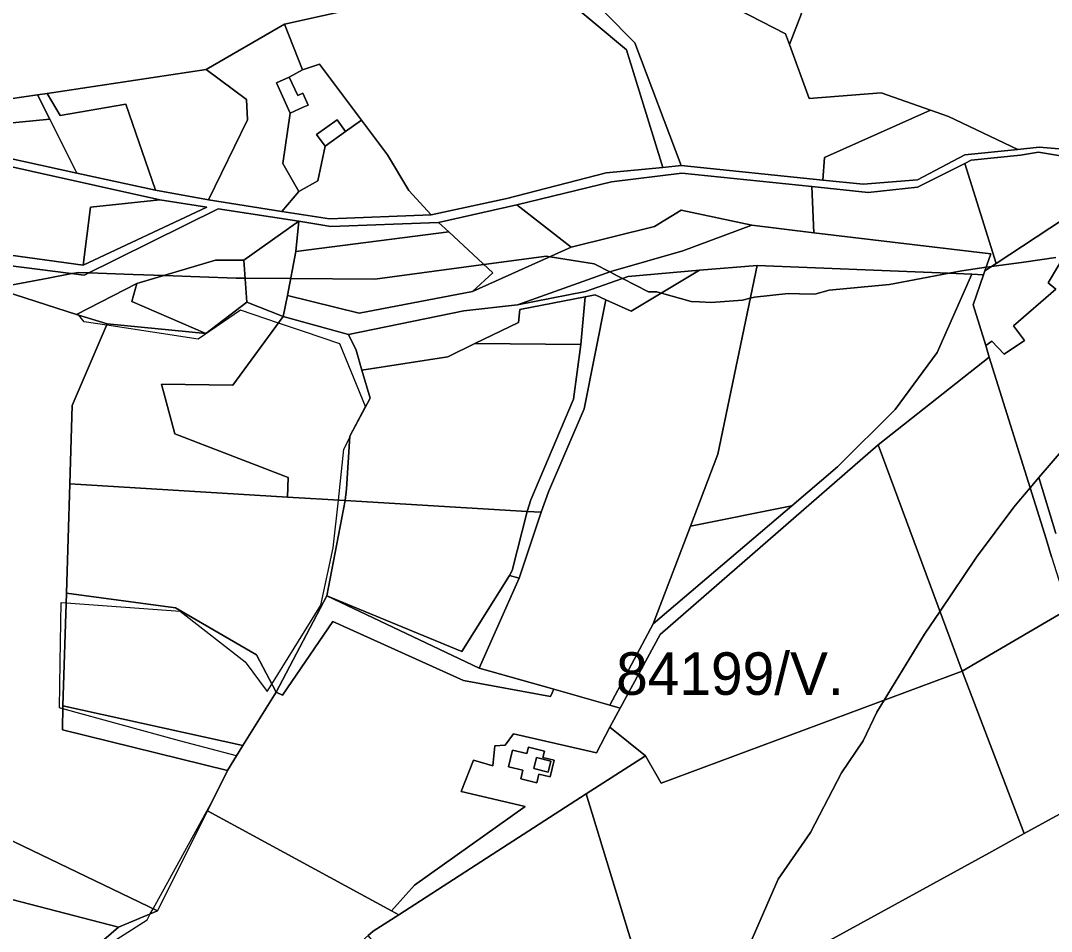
# Model space of a CAD drawing. Extents: x -477304 to -465429, y -1159113 to -1149210.
# Drawn here: x -472721.6 to -472357.9, y -1156469 to -1156147.8 of the extents above; entities that cross this region are included whole.
import ezdxf

# ---------------------------------------------------------------- set-up
doc = ezdxf.new("R2010")
doc.units = 0
for name, color, linetype in [('BPEJ_s', 7, 'Continuous'), ('orna_s', 7, 'Continuous'), ('ostatni_s', 7, 'Continuous'), ('PUPFL_s', 7, 'Continuous'), ('trav_porost_s', 7, 'Continuous'), ('zahrada_s', 7, 'Continuous')]:
    doc.layers.add(name, color=color, linetype=linetype)

msp = doc.modelspace()

# ---------------------------------------------------------------- linework, layer by layer
at = {"layer": 'BPEJ_s'}
for points in [[(-472754.25, -1156179.6), (-472715.56, -1156173.98), (-472712.19, -1156173.47), (-472656.08, -1156165.01), (-472628.5, -1156149.08), (-472538.14, -1156128.92)], [(-472754.25, -1156179.6), (-472715.56, -1156173.98), (-472712.19, -1156173.47), (-472656.08, -1156165.01), (-472628.5, -1156149.08), (-472538.14, -1156128.92)], [(-472356.28, -1156231.31), (-472367.65, -1156232.92), (-472379.07, -1156234.53), (-472379.82, -1156234.63), (-472380.9, -1156234.78), (-472389.45, -1156235.99), (-472393.92, -1156236.85), (-472403.85, -1156238.75), (-472414.98, -1156240.88), (-472436.25, -1156242.8), (-472441.35, -1156244.29), (-472446.78, -1156244.16), (-472450.71, -1156244.07), (-472462.62, -1156245.35), (-472464.11, -1156245.72), (-472466.87, -1156246.41), (-472477.93, -1156247.26), (-472481.99, -1156247.02), (-472484.95, -1156246.84), (-472495.49, -1156243.88), (-472495.93, -1156243.75), (-472497.07, -1156243.43), (-472500, -1156243.48), (-472504.6, -1156241.1), (-472509.25, -1156238.7), (-472510.86, -1156237.86), (-472513.69, -1156236.39), (-472519.18, -1156233.55), (-472534.75, -1156231.06), (-472536.07, -1156230.85), (-472558.09, -1156233.76), (-472559.05, -1156233.89), (-472596.55, -1156238.96), (-472626.28, -1156238.75), (-472642.36, -1156238.64), (-472645.54, -1156238.62), (-472658.35, -1156238.16), (-472670.95, -1156237.7), (-472681.9, -1156237.3), (-472697.47, -1156236.73), (-472701.29, -1156236.59), (-472702.5, -1156236.83), (-472703.48, -1156237.02), (-472711.8, -1156238.62), (-472730.78, -1156242.14)], [(-472694.49, -1156476.17), (-472676.96, -1156464.99), (-472675.8, -1156462.88), (-472674.8, -1156461.06), (-472653.86, -1156422.97), (-472648.55, -1156412.31), (-472645.39, -1156407.17), (-472665.48, -1156401.81), (-472706.65, -1156390.49), (-472707.88, -1156390.15), (-472707.59, -1156374.22), (-472707.2, -1156352.99), (-472705.51, -1156353.11), (-472665.31, -1156356.03), (-472642.33, -1156373.94), (-472634.56, -1156384.41), (-472632.94, -1156381.8), (-472615.64, -1156354), (-472611.25, -1156333.73), (-472609.45, -1156316.93), (-472607.53, -1156298.93), (-472605.38, -1156294.81), (-472605.35, -1156294.36), (-472599.83, -1156283.9), (-472608.89, -1156261.77), (-472621.76, -1156257.43), (-472630.61, -1156254.45), (-472644.02, -1156249.94), (-472658.89, -1156260.08), (-472691.19, -1156255.19), (-472699.09, -1156253.99), (-472701.03, -1156251.65), (-472701.87, -1156251.39), (-472730.78, -1156242.14), (-472711.8, -1156238.62), (-472703.48, -1156237.02), (-472702.5, -1156236.83), (-472701.29, -1156236.59), (-472697.47, -1156236.73), (-472681.9, -1156237.3), (-472670.95, -1156237.7), (-472658.35, -1156238.16), (-472645.54, -1156238.62), (-472642.36, -1156238.64), (-472626.28, -1156238.75), (-472596.55, -1156238.96), (-472559.05, -1156233.89), (-472558.09, -1156233.76), (-472536.07, -1156230.85), (-472534.75, -1156231.06), (-472519.18, -1156233.55), (-472513.69, -1156236.39), (-472510.86, -1156237.86), (-472509.25, -1156238.7), (-472504.6, -1156241.1), (-472500, -1156243.48), (-472497.07, -1156243.43), (-472495.93, -1156243.75), (-472495.49, -1156243.88), (-472484.95, -1156246.84), (-472481.99, -1156247.02), (-472477.93, -1156247.26), (-472466.87, -1156246.41)], [(-472466.87, -1156246.41), (-472464.11, -1156245.72), (-472462.62, -1156245.35), (-472450.71, -1156244.07), (-472446.78, -1156244.16), (-472441.35, -1156244.29), (-472436.25, -1156242.8), (-472414.98, -1156240.88), (-472403.85, -1156238.75), (-472393.92, -1156236.85), (-472389.45, -1156235.99), (-472380.9, -1156234.78), (-472379.82, -1156234.63), (-472379.07, -1156234.53), (-472367.65, -1156232.92), (-472356.28, -1156231.31)], [(-472694.49, -1156476.17), (-472676.96, -1156464.99), (-472675.8, -1156462.88), (-472674.8, -1156461.06), (-472653.86, -1156422.97), (-472648.55, -1156412.31), (-472645.39, -1156407.17), (-472665.48, -1156401.81), (-472706.65, -1156390.49), (-472707.88, -1156390.15), (-472707.59, -1156374.22), (-472707.2, -1156352.99), (-472705.51, -1156353.11), (-472665.31, -1156356.03), (-472642.33, -1156373.94), (-472634.56, -1156384.41), (-472632.94, -1156381.8), (-472615.64, -1156354), (-472611.25, -1156333.73), (-472609.45, -1156316.93), (-472607.53, -1156298.93), (-472605.38, -1156294.81), (-472605.35, -1156294.36), (-472599.83, -1156283.9), (-472608.89, -1156261.77), (-472621.76, -1156257.43), (-472630.61, -1156254.45), (-472644.02, -1156249.94), (-472658.89, -1156260.08), (-472691.19, -1156255.19), (-472699.09, -1156253.99), (-472701.03, -1156251.65), (-472701.87, -1156251.39), (-472730.78, -1156242.14)], [(-472356.28, -1156328.72), (-472362.26, -1156308.89), (-472345.64, -1156289.59)], [(-472345.64, -1156289.59), (-472362.26, -1156308.89)], [(-472463.47, -1156471.64), (-472454.32, -1156450.58), (-472442.84, -1156434.21), (-472431.99, -1156413.15), (-472424.33, -1156401.88), (-472419.44, -1156391.67), (-472416.89, -1156387.5), (-472402.64, -1156364.24), (-472397.17, -1156356.1), (-472384.35, -1156337.01), (-472371.17, -1156319.36), (-472369.35, -1156317.23), (-472365.39, -1156312.58), (-472362.26, -1156308.89), (-472356.28, -1156328.72)], [(-472362.26, -1156308.89), (-472365.39, -1156312.58), (-472369.35, -1156317.23), (-472371.17, -1156319.36), (-472384.35, -1156337.01), (-472397.17, -1156356.1), (-472402.64, -1156364.24), (-472416.89, -1156387.5), (-472419.44, -1156391.67), (-472424.33, -1156401.88), (-472431.99, -1156413.15), (-472442.84, -1156434.21), (-472454.32, -1156450.58), (-472463.47, -1156471.64)]]:
    msp.add_lwpolyline(points, dxfattribs=at)
at = {"layer": 'orna_s'}
for points in [[(-472306.6, -1156145.88), (-472320.77, -1156154.46), (-472331.03, -1156167.92), (-472335.26, -1156170.79), (-472336.81, -1156169.85), (-472343.02, -1156178.12), (-472352.73, -1156185.49), (-472348.77, -1156190.71), (-472347.2, -1156189.52), (-472343.8, -1156193.97), (-472362.25, -1156192.44), (-472369.7, -1156193.25), (-472394.23, -1156181.54), (-472400.57, -1156179.39), (-472417.89, -1156173.24), (-472443.37, -1156175.24), (-472450.31, -1156156.23), (-472446.05, -1156145.32)], [(-472357.81, -1156336.86), (-472359.78, -1156330.55), (-472379.81, -1156266.43), (-472381.06, -1156262.33), (-472378.86, -1156260.82), (-472374.52, -1156265.44), (-472367.36, -1156260.65), (-472371.2, -1156255.39), (-472356.29, -1156242.56), (-472359.07, -1156240.29), (-472348.05, -1156221.92)]]:
    msp.add_lwpolyline(points, dxfattribs=at)
at = {"layer": 'ostatni_s'}
for points in [[(-472617.12, -1156187.93), (-472614.16, -1156192.07), (-472616.73, -1156204.26), (-472623.41, -1156208.09), (-472629.07, -1156198.2), (-472626.4, -1156180.44), (-472621.87, -1156178.36), (-472620.1, -1156177.54), (-472622.01, -1156173.39), (-472623.79, -1156174.2), (-472626.79, -1156167.67), (-472622.08, -1156165.16), (-472616.12, -1156163.09), (-472601.3, -1156182.88), (-472606.94, -1156186.91), (-472609.9, -1156182.77)], [(-472631.32, -1156169.75), (-472626.79, -1156167.67), (-472623.79, -1156174.2), (-472622.01, -1156173.39), (-472620.1, -1156177.54), (-472621.87, -1156178.36), (-472626.4, -1156180.44)], [(-472617.12, -1156187.93), (-472609.9, -1156182.77), (-472606.94, -1156186.91), (-472614.16, -1156192.07)], [(-472362.45, -1156194.22), (-472344.16, -1156197.23), (-472334.36, -1156192.87), (-472330.69, -1156193.68), (-472323.27, -1156198.26), (-472324.73, -1156207.32), (-472349.13, -1156214.9), (-472377.41, -1156233.43), (-472388.42, -1156198.16), (-472386.14, -1156197.01), (-472368.83, -1156195.18)], [(-472628.91, -1156252.13), (-472627.45, -1156244.71), (-472602.13, -1156251), (-472562.11, -1156243.37), (-472527.32, -1156227.72), (-472497.91, -1156220.43), (-472488.45, -1156214.68), (-472463.54, -1156219.97), (-472487.91, -1156228.99), (-472513.29, -1156236.25), (-472546.24, -1156248.06), (-472565.21, -1156250.13), (-472605.83, -1156258.48)], [(-472397.13, -1156236.69), (-472461.69, -1156234.13), (-472482.06, -1156235.85), (-472507.21, -1156237.98), (-472522.25, -1156243.28), (-472546.24, -1156248.06), (-472513.29, -1156236.25), (-472487.91, -1156228.99), (-472463.54, -1156219.97), (-472441.66, -1156222.63), (-472379.28, -1156230.01), (-472381.32, -1156236.02), (-472381.81, -1156237.45), (-472385.94, -1156237.24)], [(-472534.77, -1156414.55), (-472538.7, -1156413.59), (-472539.43, -1156416.59), (-472545.07, -1156415.22), (-472544.34, -1156412.22), (-472549.4, -1156410.98), (-472547.96, -1156405.09), (-472542.9, -1156406.33), (-472542.34, -1156404.04), (-472536.71, -1156405.41), (-472537.27, -1156407.7), (-472533.33, -1156408.66)], [(-472535.4, -1156412.85), (-472534.46, -1156408.98), (-472539.52, -1156407.71), (-472540.47, -1156411.59)], [(-472540.47, -1156411.59), (-472539.52, -1156407.71), (-472534.46, -1156408.98), (-472535.4, -1156412.85)]]:
    msp.add_lwpolyline(points, close=True, dxfattribs=at)
for points in [[(-472344.16, -1156197.23), (-472362.45, -1156194.22), (-472368.83, -1156195.18), (-472386.14, -1156197.01), (-472388.42, -1156198.16), (-472405.12, -1156206.55), (-472422.49, -1156208.43), (-472442.46, -1156206.34), (-472488.26, -1156201.55), (-472513.14, -1156204.6), (-472546.48, -1156212.79), (-472574.12, -1156218.95), (-472612.05, -1156220.34), (-472623.44, -1156218.56), (-472651.82, -1156214.14), (-472699.16, -1156237.57), (-472797.79, -1156224.95)], [(-472739.28, -1156193.3), (-472701.72, -1156201.53), (-472673.93, -1156207.61), (-472655.24, -1156211.02), (-472629.42, -1156215.07), (-472612.58, -1156217.71), (-472576.76, -1156216.29), (-472550, -1156210.52), (-472515.01, -1156201.45), (-472494.98, -1156199.54), (-472488.5, -1156198.92), (-472438.47, -1156204.03), (-472424.34, -1156205.48), (-472405.1, -1156203.89), (-472388.43, -1156195.08), (-472369.7, -1156193.25), (-472362.25, -1156192.44), (-472343.8, -1156193.97)], [(-472755.08, -1156226.37), (-472699.46, -1156234.01), (-472655.88, -1156213.55), (-472672.4, -1156210.94), (-472740.68, -1156195.85)]]:
    msp.add_lwpolyline(points, dxfattribs=at)
at = {"layer": 'PUPFL_s'}
for points in [[(-472437.99, -1156196.01), (-472438.47, -1156204.03), (-472488.5, -1156198.92), (-472504.8, -1156155.61), (-472525.85, -1156134.23), (-472535.35, -1156119.39), (-472566.18, -1156125.99), (-472596.62, -1156079.6), (-472538.91, -1156069.82), (-472584.32, -1156088.34), (-472577.08, -1156100.48), (-472564.01, -1156122.32), (-472534.17, -1156116.61), (-472497.69, -1156135.92), (-472494.23, -1156130.49), (-472451.69, -1156152.44), (-472450.31, -1156156.23), (-472443.37, -1156175.24), (-472417.89, -1156173.24), (-472400.57, -1156179.39)], [(-472850.56, -1156204.67), (-472634.3, -1156085.9), (-472596.62, -1156079.6), (-472566.18, -1156125.99), (-472535.35, -1156119.39), (-472525.85, -1156134.23), (-472504.8, -1156155.61), (-472488.5, -1156198.92), (-472494.98, -1156199.54), (-472507.78, -1156158.06), (-472531.26, -1156138.35), (-472536.49, -1156128.55), (-472628.5, -1156149.08), (-472656.08, -1156165.01), (-472712.19, -1156173.47), (-472715.56, -1156173.98), (-472754.25, -1156179.6), (-472760.13, -1156184.93), (-472762.54, -1156187.11), (-472779.89, -1156186.92), (-472797.18, -1156190.62), (-472836.19, -1156198.97), (-472851.22, -1156206.37)], [(-472457.88, -1156132.45), (-472446.05, -1156145.32), (-472450.31, -1156156.23), (-472451.69, -1156152.44), (-472494.23, -1156130.49)], [(-472356.29, -1156242.56), (-472371.2, -1156255.39), (-472367.36, -1156260.65), (-472374.52, -1156265.44), (-472378.86, -1156260.82), (-472381.06, -1156262.33), (-472385.43, -1156248.04), (-472381.81, -1156237.45), (-472381.32, -1156236.02), (-472377.41, -1156233.43), (-472349.13, -1156214.9), (-472324.73, -1156207.32), (-472323.27, -1156198.26), (-472319.53, -1156198.72), (-472319.48, -1156209.42), (-472326.46, -1156212.48), (-472348.05, -1156221.92), (-472359.07, -1156240.29)], [(-472795.42, -1156272.52), (-472806.88, -1156326.38), (-472829.43, -1156340.79), (-472862.8, -1156373.32), (-472856.05, -1156374.79), (-472855.32, -1156391.08), (-472860.9, -1156392.25), (-472857.08, -1156414.67), (-472783.69, -1156403.4), (-472780.72, -1156422.2), (-472766.14, -1156417.35), (-472763.7, -1156422.02), (-472745.95, -1156426.91), (-472673.24, -1156461.81), (-472686.97, -1156467.54), (-472899.78, -1156412.46), (-472863.16, -1156211.61), (-472850.56, -1156204.67), (-472851.22, -1156206.37), (-472862.23, -1156226.24), (-472855.75, -1156241.42), (-472823.38, -1156239.43), (-472797.79, -1156224.95), (-472797.09, -1156241.69)], [(-472766.14, -1156417.35), (-472780.72, -1156422.2), (-472783.69, -1156403.4), (-472784.76, -1156392.72), (-472729.76, -1156381.6), (-472745.94, -1156306.31), (-472745.34, -1156237.48), (-472701.87, -1156251.39), (-472691.02, -1156254.78), (-472703.36, -1156283.5), (-472704.22, -1156311.22), (-472705.41, -1156349.79), (-472706.63, -1156389.44), (-472706.78, -1156397.96), (-472648.55, -1156412.31), (-472655.64, -1156426.53), (-472673.24, -1156461.81), (-472745.95, -1156426.91), (-472763.7, -1156422.02)], [(-472522.25, -1156243.28), (-472507.21, -1156237.98), (-472482.06, -1156235.85), (-472506.14, -1156250.25), (-472515.11, -1156246.22), (-472518.9, -1156244.49), (-472522.42, -1156245.19), (-472545.41, -1156249.71), (-472545.89, -1156254.21), (-472561.27, -1156261.71), (-472570.82, -1156266.36), (-472601.19, -1156271.05), (-472603.19, -1156263.97), (-472605.83, -1156258.48), (-472565.21, -1156250.13), (-472546.24, -1156248.06)], [(-472498.44, -1156360.61), (-472449.49, -1156318.95), (-472433.31, -1156305.17), (-472413.02, -1156285), (-472398.2, -1156264.85), (-472385.94, -1156237.24), (-472381.81, -1156237.45), (-472385.43, -1156248.04), (-472381.06, -1156262.33), (-472379.81, -1156266.43), (-472418.98, -1156297.42), (-472495.93, -1156364.31), (-472510.04, -1156390.25), (-472513.64, -1156389.2)], [(-472627.22, -1156308.93), (-472627.39, -1156315.85), (-472704.22, -1156311.22), (-472703.36, -1156283.5), (-472691.02, -1156254.78), (-472656.25, -1156258.16), (-472641.72, -1156247.08), (-472628.91, -1156252.13), (-472646.63, -1156276.32), (-472671.85, -1156276.02), (-472667.09, -1156293.57)], [(-472606.6, -1156312.91), (-472607.03, -1156317.08), (-472627.39, -1156315.85), (-472627.22, -1156308.93), (-472667.09, -1156293.57), (-472671.85, -1156276.02), (-472646.63, -1156276.32), (-472628.91, -1156252.13), (-472605.83, -1156258.48), (-472603.19, -1156263.97), (-472601.19, -1156271.05), (-472598.24, -1156280.9), (-472605.35, -1156294.36)], [(-472627.39, -1156315.85), (-472607.03, -1156317.08), (-472613.53, -1156350.7), (-472631.43, -1156384.65), (-472638.36, -1156371.53), (-472666.87, -1156354.86), (-472705.41, -1156349.79), (-472704.22, -1156311.22)], [(-472485.27, -1156326.07), (-472449.49, -1156318.95), (-472498.44, -1156360.61)], [(-472666.87, -1156354.86), (-472638.36, -1156371.53), (-472631.43, -1156384.65), (-472643.11, -1156403.47), (-472706.63, -1156389.44), (-472705.41, -1156349.79)], [(-472706.78, -1156397.96), (-472706.63, -1156389.44), (-472643.11, -1156403.47), (-472648.55, -1156412.31)], [(-472531.75, -1156522.28), (-472536.69, -1156512.73), (-472544.29, -1156513.04), (-472552.76, -1156480.21), (-472584.39, -1156498.6), (-472591.08, -1156479.9), (-472598.95, -1156470.53), (-472597.18, -1156468.98), (-472588.13, -1156463.15), (-472555.15, -1156441.88), (-472522.05, -1156420.47), (-472496.36, -1156504.48), (-472529.01, -1156521.65)], [(-472613.1, -1156482.92), (-472626.39, -1156478.42), (-472652.77, -1156479.6), (-472690.96, -1156483.85), (-472701.75, -1156488.82), (-472710.29, -1156487.69), (-472686.97, -1156467.54), (-472673.24, -1156461.81), (-472655.64, -1156426.53), (-472590.66, -1156461.78), (-472588.13, -1156463.15), (-472597.18, -1156468.98), (-472598.95, -1156470.53)]]:
    msp.add_lwpolyline(points, close=True, dxfattribs=at)
msp.add_lwpolyline([(-472634.3, -1156085.9), (-472850.56, -1156204.67), (-472863.16, -1156211.61), (-472899.78, -1156412.46), (-472686.97, -1156467.54), (-472710.29, -1156487.69), (-472737.94, -1156513.25), (-472740.99, -1156516.02), (-472744.55, -1156518.35), (-472778.08, -1156549.66), (-472794.34, -1156563.57), (-472821.5, -1156589.09), (-472897.38, -1156655.6), (-472938.95, -1156694.18), (-472946.03, -1156689.3), (-472958.61, -1156680.63), (-473010.93, -1156644.58)], dxfattribs=at)
at = {"layer": 'trav_porost_s'}
for points in [[(-472494.98, -1156199.54), (-472515.01, -1156201.45), (-472550, -1156210.52), (-472576.76, -1156216.29), (-472584.58, -1156207.68), (-472592.12, -1156195.14), (-472601.3, -1156182.88), (-472616.12, -1156163.09), (-472622.08, -1156165.16), (-472628.5, -1156149.08), (-472536.49, -1156128.55), (-472531.26, -1156138.35), (-472507.78, -1156158.06)], [(-472629.07, -1156198.2), (-472623.41, -1156208.09), (-472629.42, -1156215.07), (-472655.24, -1156211.02), (-472641.52, -1156182.82), (-472641.92, -1156175.62), (-472656.08, -1156165.01), (-472628.5, -1156149.08), (-472622.08, -1156165.16), (-472626.79, -1156167.67), (-472631.32, -1156169.75), (-472626.4, -1156180.44)], [(-472641.92, -1156175.62), (-472641.52, -1156182.82), (-472655.24, -1156211.02), (-472673.93, -1156207.61), (-472684.38, -1156177.28), (-472707.58, -1156181.3), (-472712.19, -1156173.47), (-472656.08, -1156165.01)], [(-472673.93, -1156207.61), (-472701.72, -1156201.53), (-472711.27, -1156182.52), (-472715.56, -1156173.98), (-472712.19, -1156173.47), (-472707.58, -1156181.3), (-472684.38, -1156177.28)], [(-472754.25, -1156179.6), (-472715.56, -1156173.98), (-472711.27, -1156182.52), (-472739.04, -1156185.21), (-472739.28, -1156193.3), (-472760.13, -1156184.93)], [(-472438.47, -1156204.03), (-472437.99, -1156196.01), (-472400.57, -1156179.39), (-472394.23, -1156181.54), (-472369.7, -1156193.25), (-472388.43, -1156195.08), (-472405.1, -1156203.89), (-472424.34, -1156205.48)], [(-472711.27, -1156182.52), (-472701.72, -1156201.53), (-472739.28, -1156193.3), (-472739.04, -1156185.21)], [(-472762.54, -1156187.11), (-472740.68, -1156195.85), (-472672.4, -1156210.94), (-472696.94, -1156213.52), (-472699.46, -1156234.01), (-472755.08, -1156226.37)], [(-472442.46, -1156206.34), (-472422.49, -1156208.43), (-472405.12, -1156206.55), (-472388.42, -1156198.16), (-472377.41, -1156233.43), (-472381.32, -1156236.02), (-472379.28, -1156230.01), (-472441.66, -1156222.63)], [(-472442.46, -1156206.34), (-472441.66, -1156222.63), (-472463.54, -1156219.97), (-472488.45, -1156214.68), (-472497.91, -1156220.43), (-472527.32, -1156227.72), (-472546.48, -1156212.79), (-472513.14, -1156204.6), (-472488.26, -1156201.55)], [(-472699.46, -1156234.01), (-472696.94, -1156213.52), (-472672.4, -1156210.94), (-472655.88, -1156213.55)], [(-472570.5, -1156222.3), (-472574.12, -1156218.95), (-472546.48, -1156212.79), (-472527.32, -1156227.72), (-472562.11, -1156243.37), (-472554.9, -1156236.72)], [(-472652.75, -1156232.29), (-472680.51, -1156240.54), (-472701.87, -1156251.39), (-472745.34, -1156237.48), (-472754.43, -1156254.97), (-472774.57, -1156240.07), (-472797.09, -1156241.69), (-472797.79, -1156224.95), (-472699.16, -1156237.57), (-472651.82, -1156214.14), (-472623.44, -1156218.56), (-472642.84, -1156232.33)], [(-472642.84, -1156232.33), (-472623.44, -1156218.56), (-472624.41, -1156229.2), (-472627.45, -1156244.71), (-472628.91, -1156252.13), (-472641.72, -1156247.08)], [(-472623.44, -1156218.56), (-472612.05, -1156220.34), (-472574.12, -1156218.95), (-472570.5, -1156222.3), (-472624.41, -1156229.2)], [(-472570.5, -1156222.3), (-472554.9, -1156236.72), (-472562.11, -1156243.37), (-472602.13, -1156251), (-472627.45, -1156244.71), (-472624.41, -1156229.2)], [(-472680.51, -1156240.54), (-472652.75, -1156232.29), (-472642.84, -1156232.33), (-472641.72, -1156247.08), (-472656.25, -1156258.16), (-472682.27, -1156246.81)], [(-472535.28, -1156313.96), (-472522.73, -1156284.75), (-472515.11, -1156246.22), (-472506.14, -1156250.25), (-472482.06, -1156235.85), (-472461.69, -1156234.13), (-472475.58, -1156300.67), (-472485.27, -1156326.07), (-472498.44, -1156360.61), (-472513.64, -1156389.2), (-472533.46, -1156383.61), (-472559.8, -1156376.18), (-472545.69, -1156344.5), (-472537.95, -1156321.2)], [(-472398.2, -1156264.85), (-472413.02, -1156285), (-472433.31, -1156305.17), (-472449.49, -1156318.95), (-472485.27, -1156326.07), (-472475.58, -1156300.67), (-472461.69, -1156234.13), (-472397.13, -1156236.69), (-472385.94, -1156237.24)], [(-472656.25, -1156258.16), (-472691.02, -1156254.78), (-472701.87, -1156251.39), (-472680.51, -1156240.54), (-472682.27, -1156246.81)], [(-472561.27, -1156261.71), (-472545.89, -1156254.21), (-472545.41, -1156249.71), (-472522.42, -1156245.19), (-472523.92, -1156262.01)], [(-472542.89, -1156320.95), (-472541.54, -1156316.76), (-472526.49, -1156281.34), (-472523.92, -1156262.01), (-472522.42, -1156245.19), (-472518.9, -1156244.49), (-472515.11, -1156246.22), (-472522.73, -1156284.75), (-472535.28, -1156313.96), (-472537.95, -1156321.2)], [(-472570.82, -1156266.36), (-472561.27, -1156261.71), (-472523.92, -1156262.01), (-472526.49, -1156281.34), (-472541.54, -1156316.76), (-472542.89, -1156320.95), (-472607.03, -1156317.08), (-472606.6, -1156312.91), (-472605.35, -1156294.36), (-472598.24, -1156280.9), (-472601.19, -1156271.05)], [(-472418.98, -1156297.42), (-472379.81, -1156266.43), (-472359.78, -1156330.55), (-472357.81, -1156336.86), (-472352.01, -1156355.41), (-472389.31, -1156377.26)], [(-472495.6, -1156416.72), (-472501.07, -1156407.1), (-472513.7, -1156396.98), (-472510.04, -1156390.25), (-472495.93, -1156364.31), (-472418.98, -1156297.42), (-472389.31, -1156377.26)], [(-472565.88, -1156370.27), (-472613.53, -1156350.7), (-472607.03, -1156317.08), (-472542.89, -1156320.95), (-472548.08, -1156341.76), (-472549.13, -1156343.45)], [(-472545.69, -1156344.5), (-472549.13, -1156343.45), (-472548.08, -1156341.76), (-472542.89, -1156320.95), (-472537.95, -1156321.2)], [(-472545.69, -1156344.5), (-472559.8, -1156376.18), (-472613.53, -1156350.7), (-472565.88, -1156370.27), (-472549.13, -1156343.45)], [(-472565.25, -1156380.57), (-472611.4, -1156359.69), (-472629.13, -1156385.75), (-472631.43, -1156384.65), (-472613.53, -1156350.7), (-472559.8, -1156376.18), (-472533.46, -1156383.61), (-472534.6, -1156386.16)], [(-472328.61, -1156413.2), (-472337.96, -1156418.34), (-472344.91, -1156422.16), (-472367.51, -1156434.56), (-472389.31, -1156377.26), (-472352.01, -1156355.41)], [(-472561.78, -1156408.65), (-472566.11, -1156419.68), (-472543.56, -1156425.03), (-472582.58, -1156452.7), (-472590.66, -1156461.78), (-472655.64, -1156426.53), (-472648.55, -1156412.31), (-472643.11, -1156403.47), (-472631.43, -1156384.65), (-472629.13, -1156385.75), (-472611.4, -1156359.69), (-472565.25, -1156380.57), (-472534.6, -1156386.16), (-472533.46, -1156383.61), (-472513.64, -1156389.2), (-472510.04, -1156390.25), (-472513.7, -1156396.98), (-472518.39, -1156406.05), (-472547.68, -1156399.33), (-472550.59, -1156403.35), (-472554.29, -1156403.53), (-472554.94, -1156410.64)], [(-472367.51, -1156434.56), (-472380, -1156441.42), (-472421.57, -1156464.24), (-472461.88, -1156486.38), (-472474.53, -1156493.02), (-472477.32, -1156494.49), (-472496.36, -1156504.48), (-472522.05, -1156420.47), (-472501.07, -1156407.1), (-472495.6, -1156416.72), (-472389.31, -1156377.26)], [(-472554.94, -1156410.64), (-472554.29, -1156403.53), (-472550.59, -1156403.35), (-472547.68, -1156399.33), (-472518.39, -1156406.05), (-472513.7, -1156396.98), (-472501.07, -1156407.1), (-472522.05, -1156420.47), (-472555.15, -1156441.88), (-472588.13, -1156463.15), (-472590.66, -1156461.78), (-472582.58, -1156452.7), (-472543.56, -1156425.03), (-472566.11, -1156419.68), (-472561.78, -1156408.65)], [(-472544.34, -1156412.22), (-472545.07, -1156415.22), (-472539.43, -1156416.59), (-472538.7, -1156413.59), (-472534.77, -1156414.55), (-472533.33, -1156408.66), (-472537.27, -1156407.7), (-472536.71, -1156405.41), (-472542.34, -1156404.04), (-472542.9, -1156406.33), (-472547.96, -1156405.09), (-472549.4, -1156410.98)], [(-472293.07, -1156526.4), (-472291.38, -1156529.79), (-472303.23, -1156554.32), (-472309.34, -1156558.68), (-472313.25, -1156561.47), (-472320.55, -1156566.67), (-472320.83, -1156566.61), (-472340.42, -1156562.34), (-472351.41, -1156566.44), (-472382.15, -1156577.93), (-472394.76, -1156582.64), (-472397.11, -1156583.52), (-472400.56, -1156584.81), (-472400.87, -1156584.16), (-472407.68, -1156570.97), (-472429.31, -1156548.46), (-472458.36, -1156546.45), (-472474.53, -1156493.02), (-472461.88, -1156486.38), (-472421.57, -1156464.24), (-472380, -1156441.42), (-472367.51, -1156434.56), (-472344.91, -1156422.16)]]:
    msp.add_lwpolyline(points, close=True, dxfattribs=at)
at = {"layer": 'zahrada_s'}
msp.add_lwpolyline([(-472614.16, -1156192.07), (-472606.94, -1156186.91), (-472601.3, -1156182.88), (-472592.12, -1156195.14), (-472584.58, -1156207.68), (-472576.76, -1156216.29), (-472612.58, -1156217.71), (-472629.42, -1156215.07), (-472623.41, -1156208.09), (-472616.73, -1156204.26)], close=True, dxfattribs=at)

# ---------------------------------------------------------------- texts
at = {"layer": 'BPEJ_s'}
msp.add_text('84199/V.', height=15, dxfattribs=at).set_placement((-472511.45, -1156385.6))

doc.saveas('drawing.dxf')
